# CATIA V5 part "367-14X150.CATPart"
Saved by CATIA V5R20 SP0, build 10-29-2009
Part number: 367-14X150
Definition: NONE
Nomenclature: 367-14X150
Source: Unknown
Description: 367-14X150
Bounding box of the stored display mesh (mm): x 0 to 150, y -14 to 14, z -14 to 14
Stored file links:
  C:\Users\Utente\Desktop\IO LAVORO\3D X SITO CF\X SITO\PLASTICA\3D files 367\367-14X150.CATPart
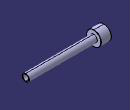
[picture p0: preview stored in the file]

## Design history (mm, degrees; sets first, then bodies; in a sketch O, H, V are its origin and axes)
Body1 "367-14X150" (main body)
  Solid1: solid without history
